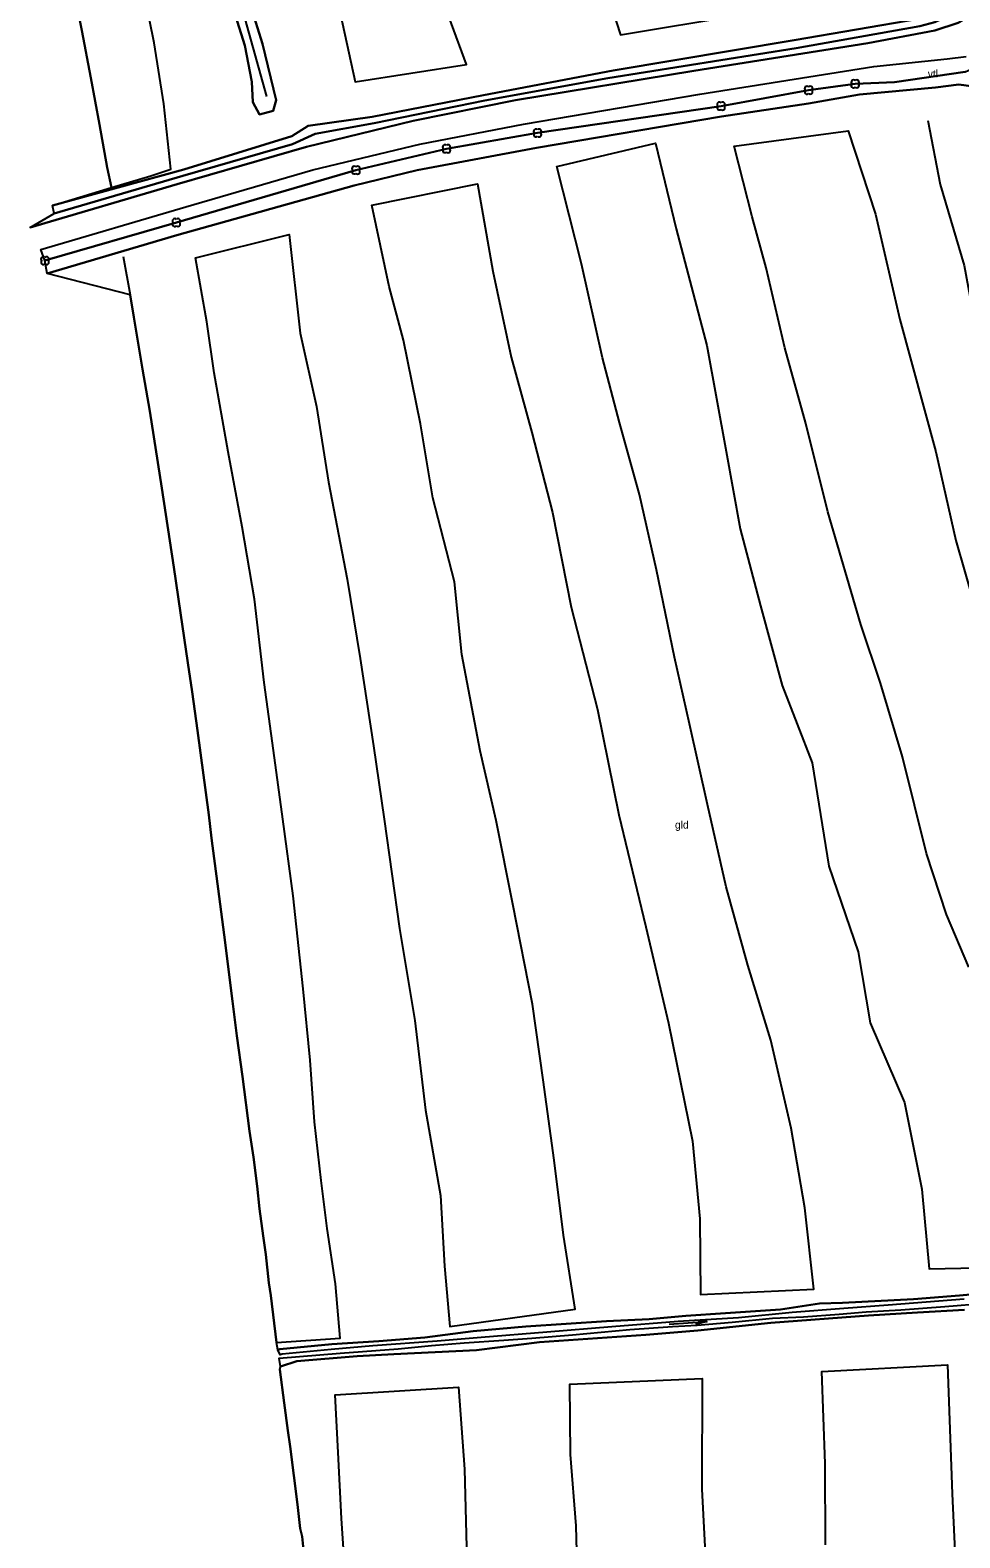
# Model space of a CAD drawing. Extents: x 154825 to 158680, y 370717 to 378075.
# Drawn here: x 157033.3 to 157154.5, y 374055.9 to 374252.3 of the extents above; entities that cross this region are included whole.
import ezdxf

# ---------------------------------------------------------------- set-up
doc = ezdxf.new("R2010")
doc.units = 0
for name, color, linetype in [('boom', 7, 'Continuous'), ('grasland_productiegrasl(vs)', 7, 'Continuous'), ('greppel - midden sloot', 7, 'Continuous'), ('hoogteverschillijn', 7, 'Continuous'), ('insteek sloot', 7, 'Continuous'), ('kant onverhard', 7, 'Continuous'), ('Sloot bodem', 7, 'Continuous'), ('stroomrichting  watergangen', 7, 'Continuous'), ('talud(boven)', 7, 'Continuous'), ('talud(onder)', 7, 'Continuous'), ('verharding algemeen', 7, 'Continuous'), ('vlak_Grasland', 7, 'Continuous'), ('vlak_Grazige_vegetatie', 7, 'Continuous')]:
    doc.layers.add(name, color=color, linetype=linetype)

msp = doc.modelspace()

# ---------------------------------------------------------------- linework, layer by layer
at = {"layer": 'boom'}
for points in [[(157123.33, 374242.38), (157099.42, 374238.87), (157087.56, 374236.82)], [(157035.23, 374222.25), (157052.36, 374227.2), (157075.76, 374234.03)]]:
    msp.add_lwpolyline(points, dxfattribs=at)
for centre, start, end in [((157134.52, 374244.65), 45, 225), ((157134.95, 374244.65), 315, 135), ((157140.59, 374245.48), 45, 225), ((157140.59, 374245.06), 134.7431, 315), ((157141.01, 374245.48), 315, 135), ((157141.01, 374245.06), 225, 45), ((157123.12, 374242.59), 45, 225), ((157123.54, 374242.59), 315, 135), ((157134.52, 374244.23), 134.7431, 315), ((157134.95, 374244.23), 225, 45), ((157123.12, 374242.16), 134.7431, 315), ((157123.54, 374242.16), 225, 45), ((157099.21, 374239.08), 45, 225), ((157099.21, 374238.65), 134.7431, 315), ((157099.63, 374239.08), 315, 135), ((157099.63, 374238.65), 225, 45), ((157087.35, 374237.03), 45, 225), ((157087.35, 374236.6), 134.7431, 315), ((157087.77, 374237.03), 315, 135), ((157087.77, 374236.6), 225, 45), ((157075.54, 374234.24), 45, 225), ((157075.54, 374233.82), 134.7431, 315), ((157075.97, 374234.24), 315, 135), ((157075.97, 374233.82), 225, 45), ((157052.15, 374227.41), 45, 225), ((157052.15, 374226.99), 134.7431, 315), ((157052.57, 374227.41), 315, 135), ((157052.57, 374226.99), 225, 45), ((157035.01, 374222.45), 45, 225), ((157035.01, 374222.03), 134.7431, 315), ((157035.44, 374222.45), 315, 135), ((157035.44, 374222.03), 225, 45)]:
    msp.add_arc(centre, 0.3, start, end, dxfattribs=at)
at = {"layer": 'greppel - midden sloot'}
msp.add_lwpolyline([(157061.27, 374253.74), (157064.09, 374243.61)], dxfattribs=at)
at = {"layer": 'hoogteverschillijn'}
for points in [[(157106.53, 374263.07), (157110.22, 374251.66), (157125.91, 374254.27)], [(157039.58, 374254.62), (157040.02, 374252.21), (157041.2, 374246.06), (157042.35, 374239.96), (157043.33, 374234.36), (157043.9, 374231.78), (157049.01, 374233.31), (157051.62, 374234.17), (157050.73, 374242.67), (157049.47, 374250.6), (157047.71, 374259.21)], [(157073.17, 374256.89), (157075.65, 374245.55), (157090.16, 374247.8), (157086.26, 374258.43)], [(157155.63, 374130.21), (157152.7, 374137.05), (157150.11, 374145.02), (157146.96, 374157.59), (157144.09, 374167.19), (157141.55, 374174.84), (157137.23, 374189.53), (157134.38, 374201.01), (157131.65, 374210.87), (157129.2, 374221.31), (157127.37, 374227.96), (157125.02, 374237.17), (157139.89, 374239.17), (157143.45, 374228.31), (157146.65, 374214.56), (157151.32, 374197.34), (157153.91, 374185.78), (157156.29, 374177.64)], [(157150.26, 374240.5), (157151.88, 374232.18), (157155.02, 374221.61), (157157.33, 374209.16), (157159.85, 374196.43), (157161.62, 374186.88), (157164.28, 374174.31), (157168.47, 374155.99)], [(157045.41, 374222.79), (157046.35, 374217.77), (157046.8, 374214.87), (157047.93, 374208.1), (157048.88, 374202.64), (157050.45, 374192.59), (157052.02, 374182.32), (157052.9, 374176.35), (157053.85, 374169.87), (157054.4, 374166.09), (157055.12, 374161.03), (157056.59, 374150.07), (157056.92, 374147.01), (157057.95, 374139.4), (157058.59, 374134.41), (157059.68, 374125.8), (157060.25, 374121.28), (157060.96, 374115.95), (157061.89, 374108.85), (157062.41, 374105.44), (157062.87, 374101.67), (157063.17, 374098.72), (157063.65, 374095.21), (157064, 374092.8), (157064.4, 374089.11), (157064.67, 374087.46), (157065.42, 374081.31), (157073.7, 374081.9), (157073.08, 374088.97), (157072, 374096.16), (157071.23, 374102.41), (157070.35, 374110.05), (157069.78, 374118.09), (157068.86, 374127.38), (157067.58, 374139.52), (157066.24, 374149.5), (157065, 374158.42), (157063.81, 374167.27), (157062.52, 374178.14), (157060.91, 374187.55), (157059.11, 374197.33), (157057.27, 374207.64), (157056.33, 374214.25), (157054.84, 374222.59), (157067.07, 374225.64), (157068.48, 374212.8), (157070.6, 374203.23), (157072.2, 374193.39), (157074.61, 374180.74), (157076.3, 374170.41), (157078.03, 374159.05), (157079.42, 374149.49), (157081.43, 374135.25), (157083.44, 374123.26), (157084.81, 374111.56), (157086.77, 374100.46), (157087.28, 374091.27), (157087.99, 374083.42), (157104.34, 374085.67), (157102.8, 374095.29), (157101.57, 374105.09), (157100.17, 374115.53), (157098.77, 374125.41), (157096.19, 374138.43), (157094.04, 374149.32), (157091.95, 374158.41), (157089.55, 374170.93), (157088.59, 374180.42), (157085.79, 374191.33), (157084.17, 374200.99), (157081.97, 374211.88), (157080.08, 374218.88), (157077.83, 374229.48), (157091.59, 374232.26), (157093.59, 374220.88), (157095.97, 374209.68), (157098.66, 374199.85), (157101.38, 374189.43), (157103.79, 374177.09), (157107.22, 374163.76), (157110.03, 374150.06), (157113.53, 374135.45), (157116.47, 374122.92), (157119.6, 374107.56), (157120.56, 374097.42), (157120.67, 374087.57), (157135.42, 374088.27), (157134.25, 374098.86), (157132.47, 374109.25), (157129.8, 374120.68), (157126.83, 374130.47), (157124, 374140.67), (157121.57, 374151.38), (157119.24, 374161.89), (157117.25, 374170.61), (157114.92, 374181.97), (157112.71, 374191.78), (157110.09, 374201.16), (157107.87, 374209.6), (157105.16, 374221.81), (157101.95, 374234.51), (157114.77, 374237.53), (157117.47, 374226.39), (157121.46, 374211.18), (157124.01, 374197.38), (157125.84, 374187.29), (157128.49, 374177.27), (157131.29, 374166.88), (157135.19, 374156.84), (157137.37, 374143.38), (157141.19, 374132.22), (157142.76, 374122.95), (157147.24, 374112.56), (157149.5, 374101.28), (157150.46, 374090.92), (157166.99, 374091.25)], [(157065.83, 374077.79), (157066.4, 374073.48), (157066.9, 374069.87), (157067.19, 374067.79), (157068.12, 374060.2), (157068.48, 374057.09), (157068.73, 374056.05), (157069, 374053.42)], [(157136.94, 374054.98), (157136.89, 374065.55), (157136.45, 374077.53), (157152.85, 374078.42), (157153.43, 374061.6), (157153.96, 374050.41)], [(157104.72, 374047.51), (157104.45, 374057.44), (157103.71, 374066.71), (157103.61, 374075.9), (157120.88, 374076.62), (157120.84, 374062.23), (157121.5, 374049.75)], [(157074.38, 374050.54), (157073.87, 374058.37), (157073.42, 374067.01), (157073.04, 374074.49), (157089.1, 374075.5), (157089.88, 374064.83), (157090.2, 374052.97)]]:
    msp.add_lwpolyline(points, dxfattribs=at)
at = {"layer": 'insteek sloot'}
for points in [[(157065.37, 374243.13), (157063.58, 374250.49), (157060.96, 374258.86)], [(157060.07, 374254.14), (157061.28, 374250.25), (157062.17, 374245.52), (157062.31, 374242.87), (157063.19, 374241.3), (157064.95, 374241.75), (157065.37, 374243.13)], [(157166.66, 374088.57), (157154.4, 374087.45), (157148.42, 374086.96), (157139.17, 374086.47), (157136.15, 374086.41), (157131.06, 374085.63), (157123.91, 374085.13), (157118.73, 374084.78), (157113.95, 374084.37), (157108.39, 374084.11), (157097.89, 374083.39), (157091.01, 374082.78), (157084.72, 374081.97), (157078.72, 374081.5), (157072.61, 374081.08), (157065.82, 374080.44), (157065.57, 374080.36)], [(157065.91, 374078.21), (157068.07, 374078.9), (157075.91, 374079.52), (157080.69, 374079.8), (157091.48, 374080.3), (157099.66, 374081.35), (157113.55, 374082.32), (157120.32, 374082.9), (157129.8, 374083.86), (157142.54, 374084.83), (157148.95, 374085.21), (157155.04, 374085.59)]]:
    msp.add_lwpolyline(points, dxfattribs=at)
at = {"layer": 'kant onverhard'}
for points in [[(157033.3, 374226.58), (157052.44, 374232.19), (157069.31, 374237.05), (157083.2, 374240.44), (157096.54, 374243.15), (157119.77, 374246.98), (157142.45, 374250.55), (157151.19, 374252.23), (157154.25, 374253.23), (157155.68, 374254.08), (157156.84, 374255.53), (157157.51, 374257.17), (157157.16, 374259.22), (157153.42, 374274.78), (157148.25, 374295.8), (157142.01, 374320.31), (157136.88, 374341.27), (157130.51, 374366.59), (157125.09, 374387.8), (157121.21, 374404.51)], [(157034.7, 374223.69), (157053.57, 374229.27), (157070.14, 374234.09), (157084.07, 374237.41), (157097.59, 374240.04), (157120.56, 374243.94), (157143.26, 374247.53), (157152.81, 374248.53), (157155.26, 374248.85)]]:
    msp.add_lwpolyline(points, dxfattribs=at)
at = {"layer": 'Sloot bodem'}
for points in [[(157065.75, 374079.28), (157073.7, 374079.94), (157081.27, 374080.51), (157085.58, 374080.91), (157089.86, 374081.28), (157095.03, 374081.63), (157098.66, 374081.87), (157103.99, 374082.31), (157111.46, 374083), (157117, 374083.39), (157120.22, 374083.58), (157124.78, 374083.98), (157130.02, 374084.49), (157134.09, 374084.65), (157138.73, 374085), (157142.26, 374085.32), (157146.76, 374085.56), (157152.5, 374086), (157157.84, 374086.42)], [(157155.01, 374086.95), (157150.08, 374086.56), (157145.12, 374086.16), (157139.31, 374085.76), (157132.58, 374085.23), (157125.59, 374084.55), (157117.75, 374084.06), (157109.08, 374083.37), (157100.62, 374082.68), (157092.09, 374081.98), (157086.36, 374081.48), (157077.95, 374080.88), (157072.53, 374080.39), (157066.15, 374079.78), (157065.86, 374079.71)]]:
    msp.add_lwpolyline(points, dxfattribs=at)
at = {"layer": 'stroomrichting  watergangen'}
for p, q in [((157116.56, 374083.7), (157121.54, 374084.06)), ((157121.53, 374084.07), (157119.96, 374084.23)), ((157121.54, 374084.06), (157120.01, 374083.67))]:
    msp.add_line(p, q, dxfattribs=at)
at = {"layer": 'talud(boven)'}
for points in [[(157036.41, 374228.38), (157053.18, 374233.3), (157067.47, 374237.42), (157070.44, 374238.75), (157078.12, 374240.16), (157092.54, 374243.12), (157108.58, 374246.01), (157133.11, 374249.93), (157149.23, 374252.79), (157151.17, 374253.3), (157152.92, 374254.12), (157153.42, 374254.09)], [(157123.33, 374242.38), (157134.74, 374244.45), (157140.8, 374245.28), (157145.95, 374245.5), (157155.16, 374246.85), (157155.92, 374247.17)], [(157075.76, 374234.03), (157087.56, 374236.82)]]:
    msp.add_lwpolyline(points, dxfattribs=at)
at = {"layer": 'talud(onder)'}
for points in [[(157152.85, 374255.15), (157152.25, 374254.89), (157149.1, 374253.73), (157132.85, 374250.95), (157109.27, 374246.99), (157092.38, 374243.8), (157077.88, 374240.96), (157069.53, 374239.81), (157067.41, 374238.46), (157053.31, 374234.12), (157036.2, 374229.42)], [(157156.55, 374244.88), (157154.31, 374245.2), (157151.26, 374244.79), (157141.38, 374243.89), (157134.74, 374242.71), (157123.37, 374241), (157099.28, 374236.93), (157083.73, 374234.04), (157075.52, 374232.03), (157052.42, 374225.54), (157035.5, 374220.57)]]:
    msp.add_lwpolyline(points, dxfattribs=at)
at = {"layer": 'vlak_Grasland'}
for points in [[(157060.07, 374254.14), (157061.28, 374250.25), (157062.17, 374245.52), (157062.31, 374242.87), (157063.19, 374241.3), (157064.95, 374241.75), (157065.37, 374243.13), (157063.58, 374250.49), (157060.96, 374258.86)], [(157149.1, 374253.73), (157132.85, 374250.95), (157109.27, 374246.99), (157092.38, 374243.8), (157077.88, 374240.96), (157069.53, 374239.81), (157067.41, 374238.46), (157053.31, 374234.12), (157036.2, 374229.42), (157043.9, 374231.78), (157043.33, 374234.36), (157042.35, 374239.96), (157041.2, 374246.06), (157040.02, 374252.21), (157039.58, 374254.62)], [(157166.66, 374088.57), (157154.4, 374087.45), (157148.42, 374086.96), (157139.17, 374086.47), (157136.15, 374086.41), (157131.06, 374085.63), (157123.91, 374085.13), (157118.73, 374084.78), (157113.95, 374084.37), (157108.39, 374084.11), (157097.89, 374083.39), (157091.01, 374082.78), (157084.72, 374081.97), (157078.72, 374081.5), (157072.61, 374081.08), (157065.82, 374080.44), (157065.57, 374080.36), (157065.42, 374081.31), (157064.67, 374087.46), (157064.4, 374089.11), (157064, 374092.8), (157063.65, 374095.21), (157063.17, 374098.72), (157062.87, 374101.67), (157062.41, 374105.44), (157061.89, 374108.85), (157060.96, 374115.95), (157060.25, 374121.28), (157059.68, 374125.8), (157058.59, 374134.41), (157057.95, 374139.4), (157056.92, 374147.01), (157056.59, 374150.07), (157055.12, 374161.03), (157054.4, 374166.09), (157053.85, 374169.87), (157052.9, 374176.35), (157052.02, 374182.32), (157050.45, 374192.59), (157048.88, 374202.64), (157047.93, 374208.1), (157046.8, 374214.87), (157046.35, 374217.77), (157035.5, 374220.57), (157052.42, 374225.54), (157075.52, 374232.03), (157083.73, 374234.04), (157099.28, 374236.93), (157123.37, 374241), (157134.74, 374242.71), (157141.38, 374243.89), (157151.26, 374244.79), (157154.31, 374245.2), (157156.55, 374244.88)], [(157069, 374053.42), (157068.73, 374056.05), (157068.48, 374057.09), (157068.12, 374060.2), (157067.19, 374067.79), (157066.9, 374069.87), (157066.4, 374073.48), (157065.83, 374077.79), (157065.91, 374078.21), (157068.07, 374078.9), (157075.91, 374079.52), (157080.69, 374079.8), (157091.48, 374080.3), (157099.66, 374081.35), (157113.55, 374082.32), (157120.32, 374082.9), (157129.8, 374083.86), (157142.54, 374084.83), (157148.95, 374085.21), (157155.04, 374085.59)]]:
    msp.add_lwpolyline(points, dxfattribs=at)
at = {"layer": 'vlak_Grazige_vegetatie'}
for points in [[(157060.96, 374258.86), (157063.58, 374250.49), (157065.37, 374243.13), (157064.95, 374241.75), (157063.19, 374241.3), (157062.31, 374242.87), (157062.17, 374245.52), (157061.28, 374250.25), (157060.07, 374254.14)], [(157154.25, 374253.23), (157151.19, 374252.23), (157142.45, 374250.55), (157119.77, 374246.98), (157096.54, 374243.15), (157083.2, 374240.44), (157069.31, 374237.05), (157052.44, 374232.19), (157033.3, 374226.58), (157036.41, 374228.38), (157053.18, 374233.3), (157067.47, 374237.42), (157070.44, 374238.75), (157078.12, 374240.16), (157092.54, 374243.12), (157108.58, 374246.01), (157133.11, 374249.93), (157149.23, 374252.79)], [(157155.16, 374246.85), (157145.95, 374245.5), (157140.8, 374245.28), (157134.74, 374244.45), (157123.33, 374242.38), (157099.42, 374238.87), (157087.56, 374236.82), (157075.76, 374234.03), (157052.36, 374227.2), (157035.23, 374222.25), (157034.7, 374223.69), (157053.57, 374229.27), (157070.14, 374234.09), (157084.07, 374237.41), (157097.59, 374240.04), (157120.56, 374243.94), (157143.26, 374247.53), (157152.81, 374248.53), (157155.26, 374248.85)], [(157155.01, 374086.95), (157150.08, 374086.56), (157145.12, 374086.16), (157139.31, 374085.76), (157132.58, 374085.23), (157125.59, 374084.55), (157117.75, 374084.06), (157109.08, 374083.37), (157100.62, 374082.68), (157092.09, 374081.98), (157086.36, 374081.48), (157077.95, 374080.88), (157072.53, 374080.39), (157066.15, 374079.78), (157065.86, 374079.71), (157065.57, 374080.36), (157065.82, 374080.44), (157072.61, 374081.08), (157078.72, 374081.5), (157084.72, 374081.97), (157091.01, 374082.78), (157097.89, 374083.39), (157108.39, 374084.11), (157113.95, 374084.37), (157118.73, 374084.78), (157123.91, 374085.13), (157131.06, 374085.63), (157136.15, 374086.41), (157139.17, 374086.47), (157148.42, 374086.96), (157154.4, 374087.45), (157166.66, 374088.57)], [(157155.04, 374085.59), (157148.95, 374085.21), (157142.54, 374084.83), (157129.8, 374083.86), (157120.32, 374082.9), (157113.55, 374082.32), (157099.66, 374081.35), (157091.48, 374080.3), (157080.69, 374079.8), (157075.91, 374079.52), (157068.07, 374078.9), (157065.91, 374078.21), (157065.75, 374079.28), (157073.7, 374079.94), (157081.27, 374080.51), (157085.58, 374080.91), (157089.86, 374081.28), (157095.03, 374081.63), (157098.66, 374081.87), (157103.99, 374082.31), (157111.46, 374083), (157117, 374083.39), (157120.22, 374083.58), (157124.78, 374083.98), (157130.02, 374084.49), (157134.09, 374084.65), (157138.73, 374085), (157142.26, 374085.32), (157146.76, 374085.56), (157152.5, 374086), (157157.84, 374086.42)]]:
    msp.add_lwpolyline(points, dxfattribs=at)
for points in [[(157153.02, 374254.47), (157153.42, 374254.09), (157152.92, 374254.12), (157151.17, 374253.3), (157149.23, 374252.79), (157133.11, 374249.93), (157108.58, 374246.01), (157092.54, 374243.12), (157078.12, 374240.16), (157070.44, 374238.75), (157067.47, 374237.42), (157053.18, 374233.3), (157036.41, 374228.38), (157036.2, 374229.42), (157053.31, 374234.12), (157067.41, 374238.46), (157069.53, 374239.81), (157077.88, 374240.96), (157092.38, 374243.8), (157109.27, 374246.99), (157132.85, 374250.95), (157149.1, 374253.73), (157152.25, 374254.89), (157152.85, 374255.15)], [(157155.92, 374247.17), (157156.55, 374244.88), (157154.31, 374245.2), (157151.26, 374244.79), (157141.38, 374243.89), (157134.74, 374242.71), (157123.37, 374241), (157099.28, 374236.93), (157083.73, 374234.04), (157075.52, 374232.03), (157052.42, 374225.54), (157035.5, 374220.57), (157035.23, 374222.25), (157052.36, 374227.2), (157075.76, 374234.03), (157087.56, 374236.82), (157099.42, 374238.87), (157123.33, 374242.38), (157134.74, 374244.45), (157140.8, 374245.28), (157145.95, 374245.5), (157155.16, 374246.85)]]:
    msp.add_lwpolyline(points, close=True, dxfattribs=at)

# ---------------------------------------------------------------- texts
at = {"layer": 'grasland_productiegrasl(vs)'}
msp.add_text('gld', height=1, dxfattribs=at).set_placement((157117.33, 374148.26))
at = {"layer": 'verharding algemeen'}
msp.add_text('vtl', height=1, dxfattribs=at).set_placement((157150.27, 374246.11))

doc.saveas('drawing.dxf')
